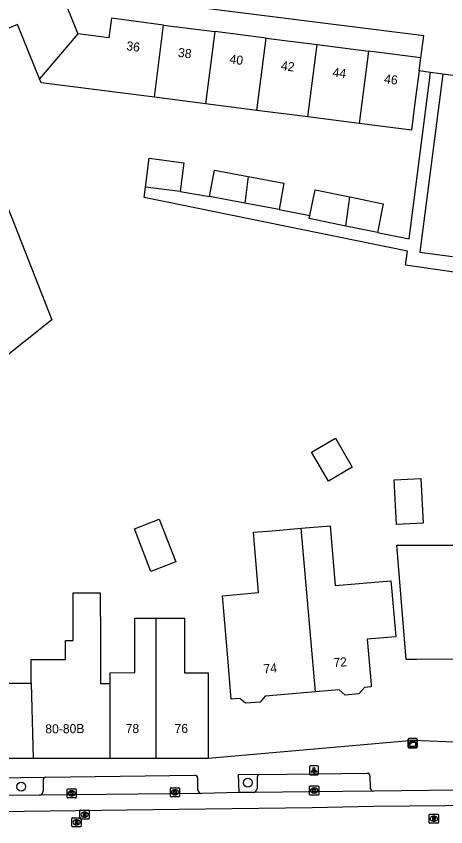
# Model space of a CAD drawing. Extents: x 159718 to 160783, y 383290 to 384030.
# Drawn here: x 160008.1 to 160055.4, y 383290.5 to 383379.9 of the extents above; entities that cross this region are included whole.
import ezdxf

# ---------------------------------------------------------------- set-up
doc = ezdxf.new("R2010")
doc.units = 0
for name, color, linetype in [('IMGEO_Boom', 7, 'Continuous'), ('IMGEO_Kast', 7, 'Continuous'), ('IMGEO_Kolk', 7, 'Continuous'), ('IMGEO_Lichtpunt', 7, 'Continuous'), ('IMGEO_Pand', 7, 'Continuous'), ('IMGEO_Pand_nummerreeks', 7, 'Continuous'), ('IMGEO_Parkeervlak_open', 7, 'Continuous'), ('IMGEO_Rijbaan_lokaal_gesloten', 7, 'Continuous'), ('IMGEO_Rioolput', 7, 'Continuous'), ('IMGEO_Voetpad_open', 7, 'Continuous')]:
    doc.layers.add(name, color=color, linetype=linetype)

msp = doc.modelspace()

# ---------------------------------------------------------------- linework, layer by layer
at = {"layer": 'IMGEO_Boom'}
for centre in [(160008.6, 383294.941), (160033.575, 383295.374)]:
    msp.add_circle(centre, 0.489, dxfattribs=at)
at = {"layer": 'IMGEO_Kast'}
for p, q in [((160051.235, 383299.307), (160051.235, 383300.148)), ((160051.235, 383300.148), (160051.235, 383299.307)), ((160051.31, 383300.232), (160052.151, 383300.232)), ((160052.151, 383300.232), (160051.31, 383300.232)), ((160052.235, 383300.157), (160052.235, 383299.316)), ((160052.235, 383299.316), (160052.235, 383300.157)), ((160052.16, 383299.232), (160051.319, 383299.232)), ((160051.319, 383299.232), (160052.16, 383299.232))]:
    msp.add_line(p, q, dxfattribs=at)
for points in [[(160051.43, 383300.022), (160052.03, 383300.022), (160052.03, 383299.937), (160051.43, 383299.937), (160051.43, 383300.022)], [(160051.43, 383299.847), (160052.03, 383299.847), (160052.03, 383299.358), (160051.43, 383299.358), (160051.43, 383299.847)]]:
    msp.add_lwpolyline(points, dxfattribs=at)
msp.add_circle((160051.514, 383299.696), 0.0377, dxfattribs=at)
for centre, start, end in [((160051.313, 383300.154), 92.4484, 184.28452), ((160051.313, 383300.154), 92.4484, 184.28452), ((160052.157, 383300.154), 2.4484, 94.28452), ((160052.157, 383300.154), 2.4484, 94.28452), ((160051.313, 383299.31), 182.4484, 274.28452), ((160051.313, 383299.31), 182.4484, 274.28452), ((160052.157, 383299.31), 272.4484, 4.28452), ((160052.157, 383299.31), 272.4484, 4.28452)]:
    msp.add_arc(centre, 0.0779, start, end, dxfattribs=at)
at = {"layer": 'IMGEO_Kolk'}
for p, q in [((160013.662, 383293.766), (160013.662, 383294.618)), ((160013.737, 383294.692), (160014.589, 383294.692)), ((160014.663, 383294.618), (160014.663, 383293.766)), ((160025.044, 383293.896), (160025.044, 383294.748)), ((160025.119, 383294.822), (160025.971, 383294.822)), ((160025.532, 383294.602), (160025.557, 383294.602)), ((160026.045, 383294.748), (160026.045, 383293.896)), ((160040.381, 383294.088), (160040.381, 383294.94)), ((160040.456, 383295.014), (160041.308, 383295.014)), ((160040.869, 383294.794), (160040.894, 383294.794)), ((160041.382, 383294.94), (160041.382, 383294.088)), ((160014.589, 383293.692), (160013.737, 383293.692)), ((160014.173, 383293.912), (160014.148, 383293.912)), ((160014.15, 383294.472), (160014.175, 383294.472)), ((160025.971, 383293.822), (160025.119, 383293.822)), ((160025.555, 383294.042), (160025.53, 383294.042)), ((160041.308, 383294.014), (160040.456, 383294.014)), ((160040.892, 383294.234), (160040.867, 383294.234))]:
    msp.add_line(p, q, dxfattribs=at)
for points in [[(160013.662, 383293.766), (160013.662, 383294.618)], [(160013.737, 383294.692), (160014.589, 383294.692)], [(160014.663, 383294.618), (160014.663, 383293.766)], [(160025.044, 383293.896), (160025.044, 383294.748)], [(160025.119, 383294.822), (160025.971, 383294.822)], [(160025.365, 383294.522), (160025.488, 383294.522), (160025.488, 383294.371), (160025.618, 383294.522), (160025.782, 383294.522), (160025.636, 383294.371), (160025.789, 383294.122), (160025.637, 383294.122), (160025.552, 383294.286), (160025.488, 383294.219), (160025.488, 383294.122), (160025.365, 383294.122), (160025.365, 383294.522)], [(160026.045, 383294.748), (160026.045, 383293.896)], [(160040.381, 383294.088), (160040.381, 383294.94)], [(160040.456, 383295.014), (160041.308, 383295.014)], [(160040.702, 383294.714), (160040.825, 383294.714), (160040.825, 383294.563), (160040.955, 383294.714), (160041.119, 383294.714), (160040.973, 383294.563), (160041.126, 383294.314), (160040.974, 383294.314), (160040.889, 383294.478), (160040.825, 383294.411), (160040.825, 383294.314), (160040.702, 383294.314), (160040.702, 383294.714)], [(160041.382, 383294.94), (160041.382, 383294.088)], [(160014.589, 383293.692), (160013.737, 383293.692)], [(160013.983, 383294.392), (160014.106, 383294.392), (160014.106, 383294.241), (160014.236, 383294.392), (160014.4, 383294.392), (160014.254, 383294.241), (160014.407, 383293.992), (160014.255, 383293.992), (160014.17, 383294.156), (160014.106, 383294.089), (160014.106, 383293.992), (160013.983, 383293.992), (160013.983, 383294.392)], [(160025.971, 383293.822), (160025.119, 383293.822)], [(160041.308, 383294.014), (160040.456, 383294.014)]]:
    msp.add_lwpolyline(points, dxfattribs=at)
for centre, start, end in [((160013.739, 383294.616), 91.55205, 178.44795), ((160013.739, 383294.616), 91.55205, 178.44795), ((160014.587, 383294.616), 1.55205, 88.44795), ((160014.587, 383294.616), 1.55205, 88.44795), ((160025.121, 383294.746), 91.55205, 178.44795), ((160025.121, 383294.746), 91.55205, 178.44795), ((160025.969, 383294.746), 1.55205, 88.44795), ((160025.969, 383294.746), 1.55205, 88.44795), ((160040.458, 383294.938), 91.55205, 178.44795), ((160040.458, 383294.938), 91.55205, 178.44795), ((160041.306, 383294.938), 1.55205, 88.44795), ((160041.306, 383294.938), 1.55205, 88.44795), ((160013.739, 383293.768), 181.55205, 268.44795), ((160013.739, 383293.768), 181.55205, 268.44795), ((160014.587, 383293.768), 271.55205, 358.44795), ((160014.587, 383293.768), 271.55205, 358.44795), ((160025.121, 383293.898), 181.55205, 268.44795), ((160025.121, 383293.898), 181.55205, 268.44795), ((160025.969, 383293.898), 271.55205, 358.44795), ((160025.969, 383293.898), 271.55205, 358.44795), ((160040.458, 383294.09), 181.55205, 268.44795), ((160040.458, 383294.09), 181.55205, 268.44795), ((160041.306, 383294.09), 271.55205, 358.44795), ((160041.306, 383294.09), 271.55205, 358.44795)]:
    msp.add_arc(centre, 0.0765, start, end, dxfattribs=at)
for centre, major_axis, ratio, start_param, end_param in [((160025.531, 383294.322), (-0.387, 0.002), 0.722429, 4.712389, 7.853982), ((160025.556, 383294.322), (-0.39, 0.002), 0.717154, 1.570796, 4.712389), ((160040.868, 383294.514), (-0.387, 0.002), 0.722429, 4.712389, 7.853982), ((160040.893, 383294.514), (-0.39, 0.002), 0.717154, 1.570796, 4.712389), ((160014.149, 383294.192), (-0.387, 0.002), 0.722429, 4.712389, 7.853982), ((160014.174, 383294.192), (-0.39, 0.002), 0.717154, 1.570796, 4.712389)]:
    msp.add_ellipse(centre, major_axis=major_axis, ratio=ratio, start_param=start_param, end_param=end_param, dxfattribs=at)
at = {"layer": 'IMGEO_Lichtpunt'}
for p, q in [((160041.261, 383297.237), (160040.453, 383297.237)), ((160041.261, 383297.237), (160040.453, 383297.237)), ((160040.359, 383297.142), (160040.359, 383296.335)), ((160040.359, 383297.142), (160040.359, 383296.335)), ((160041.355, 383296.335), (160041.355, 383297.142)), ((160041.355, 383296.335), (160041.355, 383297.142)), ((160040.453, 383296.241), (160041.261, 383296.241)), ((160040.453, 383296.241), (160041.261, 383296.241))]:
    msp.add_line(p, q, dxfattribs=at)
for points in [[(160040.733, 383296.806), (160040.772, 383296.778), (160040.584, 383296.516), (160040.546, 383296.543), (160040.733, 383296.806)], [(160040.835, 383296.758), (160040.882, 383296.758), (160040.882, 383296.436), (160040.835, 383296.436), (160040.835, 383296.758)], [(160040.945, 383296.778), (160040.983, 383296.805), (160041.17, 383296.543), (160041.131, 383296.515), (160040.945, 383296.778)]]:
    msp.add_lwpolyline(points, dxfattribs=at)
msp.add_circle((160040.858, 383296.94), 0.0994, dxfattribs=at)
for centre, start, end in [((160040.453, 383297.142), 90, 180), ((160040.453, 383297.142), 90, 180), ((160041.261, 383297.142), 0, 90), ((160041.261, 383297.142), 0, 90), ((160040.453, 383296.335), 180, 270), ((160040.453, 383296.335), 180, 270), ((160041.261, 383296.335), 270, 0), ((160041.261, 383296.335), 270, 360)]:
    msp.add_arc(centre, 0.0946, start, end, dxfattribs=at)
at = {"layer": 'IMGEO_Pand'}
for points in [[(160010.953, 383387.663), (160014.825, 383377.98)], [(160010.623, 383373.014), (160008.19, 383378.998), (160006.055, 383378.145), (160003.449, 383384.662)], [(160024.297, 383378.96), (160018.539, 383379.697), (160018.263, 383377.541), (160014.825, 383377.98)], [(160023.277, 383370.982), (160024.297, 383378.96)], [(160024.297, 383378.96), (160029.935, 383378.239)], [(160014.825, 383377.98), (160010.623, 383373.014)], [(160029.935, 383378.239), (160028.915, 383370.261)], [(160035.574, 383377.518), (160029.935, 383378.239)], [(160034.553, 383369.54), (160035.574, 383377.518)], [(160035.574, 383377.518), (160041.212, 383376.797)], [(160040.191, 383368.819), (160041.212, 383376.797)], [(160041.212, 383376.797), (160046.85, 383376.076)], [(160046.85, 383376.076), (160045.829, 383368.098)], [(160052.624, 383375.337), (160046.85, 383376.076)], [(160052.439, 383373.892), (160052.624, 383375.337)], [(160052.439, 383373.892), (160051.989, 383370.378), (160051.603, 383367.359), (160045.829, 383368.098)], [(160023.277, 383370.982), (160010.8, 383372.578), (160010.623, 383373.014)], [(160028.915, 383370.261), (160023.277, 383370.982)], [(160034.553, 383369.54), (160028.915, 383370.261)], [(160040.191, 383368.819), (160034.553, 383369.54)], [(160045.829, 383368.098), (160040.191, 383368.819)], [(160022.307, 383361.071), (160022.716, 383364.252), (160026.527, 383363.761), (160026.117, 383360.58)], [(160029.361, 383360.038), (160029.896, 383362.929), (160033.619, 383362.241)], [(160033.619, 383362.241), (160033.245, 383359.319)], [(160033.619, 383362.241), (160037.546, 383361.515), (160037.011, 383358.623)], [(160002.231, 383361.493), (160005.183, 383360.991), (160006.368, 383360.79), (160011.959, 383346.418), (160006.342, 383341.94), (160004.483, 383346.591)], [(160026.117, 383360.58), (160022.307, 383361.071)], [(160040.402, 383357.932), (160040.98, 383360.769), (160044.792, 383359.992)], [(160033.245, 383359.319), (160029.361, 383360.038)], [(160044.381, 383356.782), (160044.792, 383359.992)], [(160044.792, 383359.992), (160048.486, 383359.239), (160047.842, 383356.077)], [(160037.011, 383358.623), (160033.245, 383359.319)], [(160044.381, 383356.782), (160040.336, 383357.607), (160040.402, 383357.932)], [(160047.842, 383356.077), (160044.381, 383356.782)], [(160043.217, 383333.372), (160045.081, 383330.174), (160042.469, 383328.651), (160040.604, 383331.848), (160043.217, 383333.372)], [(160052.637, 383328.937), (160052.897, 383324.006), (160049.968, 383323.851), (160049.708, 383328.783), (160052.637, 383328.937)], [(160025.64, 383319.74), (160022.893, 383318.672), (160021.068, 383323.366), (160023.815, 383324.434), (160025.64, 383319.74)], [(160041.024, 383305.392), (160035.497, 383304.926), (160034.941, 383304.268), (160033.323, 383304.132), (160032.686, 383304.67), (160031.738, 383304.59), (160031.317, 383309.573), (160030.789, 383316.006), (160034.761, 383316.344), (160034.2, 383322.999), (160036.246, 383323.172), (160039.451, 383323.443)], [(160039.451, 383323.443), (160042.643, 383323.712), (160043.2, 383317.111), (160049.346, 383317.63), (160049.446, 383316.453), (160049.866, 383311.47), (160046.731, 383311.205), (160047.15, 383306.235), (160047.175, 383305.936), (160046.411, 383305.872), (160045.812, 383305.162), (160044.313, 383305.036), (160043.63, 383305.612), (160041.024, 383305.392)], [(160041.024, 383305.392), (160039.451, 383323.443)], [(160064.042, 383303.206), (160058.424, 383303.174), (160058.423, 383303.374), (160058.39, 383309.014), (160052.17, 383308.978), (160051.031, 383308.971), (160049.996, 383321.57), (160058.076, 383321.582), (160058.112, 383315.401), (160061.534, 383315.406), (160061.557, 383311.311), (160063.996, 383311.325)], [(160009.683, 383306.364), (160009.68, 383308.972), (160013.483, 383308.976), (160013.48, 383311.06), (160014.323, 383311.061), (160014.317, 383316.311), (160017.318, 383316.315), (160017.325, 383311.064), (160017.331, 383306.308), (160018.412, 383306.309)], [(160018.412, 383306.309), (160018.411, 383307.51), (160021.128, 383307.514), (160021.124, 383311.387), (160021.122, 383313.526), (160023.458, 383313.529)], [(160023.458, 383313.529), (160026.586, 383313.532), (160026.588, 383311.394), (160026.593, 383307.503), (160029.195, 383307.507), (160029.205, 383298.058)], [(160023.487, 383298.056), (160023.461, 383311.39), (160023.458, 383313.529)], [(159999.241, 383298.046), (159999.223, 383313.243), (160005.829, 383313.244), (160005.837, 383306.359), (160009.683, 383306.364)], [(160009.683, 383306.364), (160009.914, 383298.051)], [(160018.39, 383298.054), (160018.412, 383306.309)], [(160009.914, 383298.051), (160000, 383298.047), (159999.241, 383298.046)], [(160018.39, 383298.054), (160009.914, 383298.051)], [(160023.487, 383298.056), (160018.39, 383298.054)], [(160029.205, 383298.058), (160023.487, 383298.056)]]:
    msp.add_lwpolyline(points, dxfattribs=at)
at = {"layer": 'IMGEO_Parkeervlak_open'}
for points in [[(160011.007, 383295.654), (160011.004, 383294.436)], [(160034.593, 383295.979), (160034.599, 383294.746)]]:
    msp.add_lwpolyline(points, dxfattribs=at)
for centre, radius, start, end in [((160011.345, 383295.662), 0.339, 98.91833, 181.27307), ((160034.918, 383295.95), 0.326, 100.43507, 174.90046), ((160034.143, 383294.743), 0.456, 271.37225, 0.40226), ((160010.558, 383294.427), 0.446, 272.41445, 1.09634)]:
    msp.add_arc(centre, radius, start, end, dxfattribs=at)
at = {"layer": 'IMGEO_Rijbaan_lokaal_gesloten'}
for points in [[(160059.499, 383294.598), (160047.505, 383294.448), (160047.439, 383294.447)], [(160010.577, 383293.982), (160006.567, 383293.953)], [(160028.488, 383294.189), (160014.409, 383294.041), (160010.577, 383293.982)], [(160032.6, 383294.278), (160028.488, 383294.189)], [(160034.154, 383294.287), (160032.6, 383294.278)], [(160047.439, 383294.447), (160040.647, 383294.363), (160034.154, 383294.287)], [(160059.219, 383292.845), (160047.427, 383292.731), (160040.677, 383292.583), (160025.97, 383292.419), (159997.559, 383292.063)]]:
    msp.add_lwpolyline(points, dxfattribs=at)
at = {"layer": 'IMGEO_Rioolput'}
for p, q in [((160015.077, 383291.425), (160015.077, 383292.277)), ((160015.152, 383292.351), (160016.004, 383292.351)), ((160015.565, 383292.131), (160015.59, 383292.131)), ((160016.078, 383292.277), (160016.078, 383291.425)), ((160053.641, 383291.894), (160054.493, 383291.894)), ((160014.196, 383290.584), (160014.196, 383291.436)), ((160014.271, 383291.51), (160015.123, 383291.51)), ((160014.684, 383291.29), (160014.709, 383291.29)), ((160016.004, 383291.351), (160015.152, 383291.351)), ((160015.197, 383291.436), (160015.197, 383290.584)), ((160015.588, 383291.571), (160015.563, 383291.571)), ((160053.566, 383290.968), (160053.566, 383291.82)), ((160054.077, 383291.114), (160054.052, 383291.114)), ((160054.054, 383291.674), (160054.079, 383291.674)), ((160054.567, 383291.82), (160054.567, 383290.968)), ((160015.123, 383290.51), (160014.271, 383290.51)), ((160014.707, 383290.73), (160014.682, 383290.73)), ((160054.493, 383290.894), (160053.641, 383290.894))]:
    msp.add_line(p, q, dxfattribs=at)
for points in [[(160015.077, 383291.425), (160015.077, 383292.277)], [(160015.152, 383292.351), (160016.004, 383292.351)], [(160015.666, 383292.049), (160015.414, 383292.051), (160015.414, 383291.651)], [(160015.592, 383291.97), (160015.538, 383291.97), (160015.538, 383291.889)], [(160015.538, 383291.889), (160015.59, 383291.889)], [(160016.078, 383292.277), (160016.078, 383291.425)], [(160053.641, 383291.894), (160054.493, 383291.894)], [(160014.196, 383290.584), (160014.196, 383291.436)], [(160014.271, 383291.51), (160015.123, 383291.51)], [(160014.785, 383291.208), (160014.533, 383291.21), (160014.533, 383290.81)], [(160014.533, 383290.81), (160014.657, 383290.81), (160014.657, 383290.972), (160014.668, 383290.972)], [(160014.711, 383291.129), (160014.657, 383291.129), (160014.657, 383291.048)], [(160014.657, 383291.048), (160014.709, 383291.048)], [(160014.715, 383290.943), (160014.786, 383290.81), (160014.926, 383290.81), (160014.861, 383290.936)], [(160016.004, 383291.351), (160015.152, 383291.351)], [(160015.197, 383291.436), (160015.197, 383290.584)], [(160015.414, 383291.651), (160015.538, 383291.651), (160015.538, 383291.813), (160015.549, 383291.813)], [(160015.596, 383291.784), (160015.667, 383291.651), (160015.807, 383291.651), (160015.742, 383291.777)], [(160053.566, 383290.968), (160053.566, 383291.82)], [(160054.155, 383291.592), (160053.903, 383291.594), (160053.903, 383291.194)], [(160053.903, 383291.194), (160054.027, 383291.194), (160054.027, 383291.356), (160054.038, 383291.356)], [(160054.081, 383291.513), (160054.027, 383291.513), (160054.027, 383291.432)], [(160054.027, 383291.432), (160054.079, 383291.432)], [(160054.085, 383291.327), (160054.156, 383291.194), (160054.296, 383291.194), (160054.231, 383291.32)], [(160054.567, 383291.82), (160054.567, 383290.968)], [(160015.123, 383290.51), (160014.271, 383290.51)], [(160054.493, 383290.894), (160053.641, 383290.894)]]:
    msp.add_lwpolyline(points, dxfattribs=at)
for centre, radius, start, end in [((160015.154, 383292.275), 0.0765, 91.55205, 178.44795), ((160015.154, 383292.275), 0.0765, 91.55205, 178.44795), ((160015.574, 383292.078), 0.19, 274.7715, 282.96867), ((160015.598, 383291.874), 0.0964, 77.00612, 93.18647), ((160015.612, 383291.931), 0.0378, 276.66336, 79.67722), ((160015.665, 383291.939), 0.109, 350.36119, 89.41601), ((160015.663, 383291.939), 0.112, 277.58423, 350.98172), ((160016.002, 383292.275), 0.0765, 1.55205, 88.44795), ((160016.002, 383292.275), 0.0765, 1.55205, 88.44795), ((160053.643, 383291.818), 0.0765, 91.55205, 178.44795), ((160053.643, 383291.818), 0.0765, 91.55205, 178.44795), ((160054.491, 383291.818), 0.0765, 1.55205, 88.44795), ((160054.491, 383291.818), 0.0765, 1.55205, 88.44795), ((160014.273, 383291.434), 0.0765, 91.55205, 178.44795), ((160014.273, 383291.434), 0.0765, 91.55205, 178.44795), ((160014.667, 383290.919), 0.0533, 26.02933, 88.69889), ((160014.693, 383291.237), 0.19, 274.7715, 282.96867), ((160014.717, 383291.033), 0.0964, 77.00612, 93.18647), ((160014.731, 383291.09), 0.0378, 276.66336, 79.67722), ((160014.784, 383291.098), 0.109, 350.36119, 89.41601), ((160014.782, 383291.098), 0.112, 277.58423, 350.98172), ((160014.766, 383290.883), 0.108, 29.51342, 73.79051), ((160015.154, 383291.427), 0.0765, 181.55205, 268.44795), ((160015.154, 383291.427), 0.0765, 181.55205, 268.44795), ((160015.121, 383291.434), 0.0765, 1.55205, 88.44795), ((160015.121, 383291.434), 0.0765, 1.55205, 88.44795), ((160015.548, 383291.76), 0.0533, 26.02933, 88.69889), ((160015.647, 383291.724), 0.108, 29.51342, 73.79051), ((160016.002, 383291.427), 0.0765, 271.55205, 358.44795), ((160016.002, 383291.427), 0.0765, 271.55205, 358.44795), ((160053.643, 383290.97), 0.0765, 181.55205, 268.44795), ((160053.643, 383290.97), 0.0765, 181.55205, 268.44795), ((160054.037, 383291.303), 0.0533, 26.02933, 88.69889), ((160054.063, 383291.621), 0.19, 274.7715, 282.96867), ((160054.087, 383291.417), 0.0964, 77.00612, 93.18647), ((160054.101, 383291.474), 0.0378, 276.66336, 79.67722), ((160054.154, 383291.482), 0.109, 350.36119, 89.41601), ((160054.152, 383291.482), 0.112, 277.58423, 350.98172), ((160054.136, 383291.267), 0.108, 29.51342, 73.79051), ((160054.491, 383290.97), 0.0765, 271.55205, 358.44795), ((160054.491, 383290.97), 0.0765, 271.55205, 358.44795), ((160014.273, 383290.586), 0.0765, 181.55205, 268.44795), ((160014.273, 383290.586), 0.0765, 181.55205, 268.44795), ((160015.121, 383290.586), 0.0765, 271.55205, 358.44795), ((160015.121, 383290.586), 0.0765, 271.55205, 358.44795)]:
    msp.add_arc(centre, radius, start, end, dxfattribs=at)
for centre, major_axis, ratio, start_param, end_param in [((160015.564, 383291.851), (-0.387, 0.002), 0.722429, 4.712389, 7.853982), ((160015.589, 383291.851), (-0.39, 0.002), 0.717154, 1.570796, 4.712389), ((160014.683, 383291.01), (-0.387, 0.002), 0.722429, 4.712389, 7.853982), ((160014.708, 383291.01), (-0.39, 0.002), 0.717154, 1.570796, 4.712389), ((160054.053, 383291.394), (-0.387, 0.002), 0.722429, 4.712389, 7.853982), ((160054.078, 383291.394), (-0.39, 0.002), 0.717154, 1.570796, 4.712389)]:
    msp.add_ellipse(centre, major_axis=major_axis, ratio=ratio, start_param=start_param, end_param=end_param, dxfattribs=at)
at = {"layer": 'IMGEO_Voetpad_open'}
for points in [[(160052.624, 383375.337), (160052.976, 383377.756), (160016.099, 383382.429), (160004.346, 383412.176)], [(160047.842, 383356.077), (160051.341, 383355.364), (160053.714, 383373.727)], [(160053.714, 383373.727), (160052.439, 383373.892)], [(160055.073, 383373.551), (160052.534, 383353.901), (160056.135, 383353.425)], [(160055.073, 383373.551), (160053.714, 383373.727)], [(160085.3, 383369.646), (160055.073, 383373.551)], [(160060.899, 383351.046), (160050.946, 383352.451), (160051.165, 383354.007), (160022.158, 383359.914), (160022.307, 383361.071)], [(160026.117, 383360.58), (160029.361, 383360.038)], [(160037.011, 383358.623), (160040.402, 383357.932)], [(160084.459, 383303.025), (160084.474, 383300.355), (160059.918, 383299.712), (160051.807, 383300.026), (160029.205, 383298.058)], [(160034.859, 383296.271), (160040.872, 383296.344), (160046.739, 383296.432)], [(160005.822, 383295.928), (160011.293, 383295.996)], [(160011.293, 383295.996), (160027.732, 383296.209)], [(160028.029, 383295.897), (160028.033, 383294.681)], [(160032.6, 383294.278), (160032.555, 383296.297), (160034.859, 383296.271)], [(160047.02, 383296.107), (160047.033, 383294.882)]]:
    msp.add_lwpolyline(points, dxfattribs=at)
for centre, radius, start, end in [((160046.75, 383296.158), 0.275, 349.38427, 92.31013), ((160027.725, 383295.905), 0.304, 358.47435, 88.70377), ((160028.511, 383294.667), 0.478, 178.3074, 267.2177), ((160047.467, 383294.88), 0.434, 179.78746, 266.26267)]:
    msp.add_arc(centre, radius, start, end, dxfattribs=at)

# ---------------------------------------------------------------- texts
at = {"layer": 'IMGEO_Pand_nummerreeks'}
for s, rotation, p in [('36', 352.71057, (160020.143, 383376.185)), ('38', 352.71057, (160025.827, 383375.458)), ('40', 352.71057, (160031.508, 383374.732)), ('42', 352.71057, (160037.183, 383374.006)), ('44', 352.71057, (160042.867, 383373.278)), ('46', 352.71198, (160048.548, 383372.552)), ('72', 5.05238, (160043.051, 383308.101)), ('74', 4.9389, (160035.34, 383307.43)), ('80-80B', 0.514, (160011.259, 383300.809)), ('78', 0.09822, (160020.111, 383300.845)), ('76', 0.09822, (160025.497, 383300.854))]:
    msp.add_text(s, height=1, rotation=rotation, dxfattribs=at).set_placement(p)

doc.saveas('drawing.dxf')
